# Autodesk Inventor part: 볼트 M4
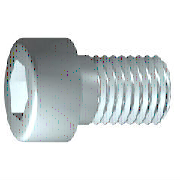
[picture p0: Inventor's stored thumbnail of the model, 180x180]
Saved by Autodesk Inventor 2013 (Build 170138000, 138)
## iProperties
IsCustomPart: 1
Created: 2015-10
Part Number: 볼트 M4
Material: 스테인리스강
Description: 6각머리 태핑 나사
Document SubType Name: Modeling
Standard: KS B 1003
Designer: mdu
Standards Organization: KS
Language: ko-KR
Size Designation: M 4 x 16
Categories: <MemberInstance><Categories><Category DisplayName="조임쇠" InternalName="e4da775c-781d-43d5-af7c-5136215cf5a6" Mnemonic="FSTN"><Category DisplayName="볼트" InternalN
Density: 8.08 g/cm^3
Mass: 2.70334 g
Surface Area: 3.81118 cm^2
Volume: 0.334572 cm^3
Author: mdu
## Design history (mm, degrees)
sketch "스케치1"
  geometry: L1 (-1, 0)-(16, 0); L2 (16, 0)-(16, 2); L3 (16, 2)-(1.75, 2); L4 (1.75, 2)-(1.32, 2); L5 (1.32, 2)-(0, 2); L6 (0, 2)-(0, 3.5); L7 (0, 3.5)-(-4, 3.5); L8 (-4, 3.5)-(-4, 1.732); L9 (-4, 1.732)-(-2, 1.732); L10 (-2, 1.732)-(-1, 0); L11 (-8, 0)-(20, 0) reference; L12 (0, -0.7)-(0, 4.2) reference; L13 (1.75, 2)-(0, 2)
  constraints: 22 end point, 6 parallel, 2 collinear, 2 perpendicular, 1 horizontal, 1 point on line
  dimensions: "d1" = 14.25 distance from line of L3.end L2 (= GEL); "d2" = 0.42952 distance of L4.end L3.end (computed from GAL); "d3" = 4 distance between parallel lines of L8 L6 (= KOH); "d4" = 2 distance of L8.end L9.end (= INTI); "d5" = 60 deg angle of L10 L1; "d6" = 4 diameter of L3 L1 (= GD); "d7" = 4 diameter of L5 L1 (= BDM); "d8" = 3.4641 diameter of L9 L1 (= 1.1547 x SW); "d9" = 7 diameter of L7 L1 (= KOD); "d26" = 16 distance between parallel lines of L12 L2 (= NLG)
revolve "본체" sketch "스케치1" stored, may be unused: angle "d10" = 90 deg
sketch "스케치2"
  geometry: L1 (0, -4.9)-(0, 4.9) reference; L2 (-4.9, 0)-(4.9, 0) reference; L3 (1.732, 0)-(0.866, -1.5); L4 (0.866, -1.5)-(-0.866, -1.5); L5 (-0.866, -1.5)-(-1.732, 0); L6 (-1.732, 0)-(-0.866, 1.5); L7 (-0.866, 1.5)-(0.866, 1.5); L8 (0.866, 1.5)-(1.732, 0); 2 further points
  constraints: 12 end point, 1 coincident, 1 horizontal alignment, 1 point on line, 12 other
extrude "슬롯" join sketch "스케치2" stored distance "d11" = 10; taper "d12" = 0 deg
workplane "Work Plane1"
fillet "Fillet2" dims "d30" = 0.1 (= R)
body "Solid1"
fillet "모깎기1" dims "d17" = 0.4 (= RR)
feature "스레드" dims "d13" = 14.25 (= GEL), "d14" = 0
chamfer "모따기1" distance "d15" = 0.42941 (= -0.5 x SPD + 0.5 x GD); stored, may be unused: second distance "d16" = 0.42941 (= GUL), angle "d27" = 45 deg
other parameters: "GD" = 4 (= NND) [user parameter; used in 2 equation terms], "NLG" = 16 [user parameter; used in 1 equation term], "GEL" = 14.25 [user parameter; used in 2 equation terms], "KOD" = 7 [user parameter; used in 1 equation term], "KOH" = 4 [user parameter; used in 1 equation term], "INTI" = 2 [user parameter; used in 1 equation term], "GAL" = 0.42941 (= 0.61345 x PTC) [user parameter; used in 1 equation term], "GUL" = 0.42941 (= 0.61345 x PTC) [user parameter; used in 1 equation term], "BDM" = 4 (= NND) [user parameter; used in 1 equation term], "SW" = 3 [user parameter; used in 2 equation terms], "RR" = 0.4 [user parameter; used in 1 equation term], "SPD" = 3.14117 (= NND - 1.2269 x PTC) [user parameter; used in 1 equation term], "d19" = 0, "d28" = 0, "d29" = 0, "R" = 0.1 [user parameter; used in 1 equation term], "PHH" = 0.2 [user parameter], "GD1" = 3.14117 (= THREADDIA - 1.2269 x PTC) [user parameter], "THREADDIA" = 4 [user parameter; used in 1 equation term], "FAWI" = 45 deg [user parameter], "TPU" = 14.28571 (computed from PTC) [user parameter], "PTC" = 0.7 [user parameter; used in 5 equation terms], "NND" = 4 [user parameter; used in 3 equation terms], "TOA" = 30 deg [user parameter], "E0" = 3.465 (= 1.155 x SW) [user parameter]
